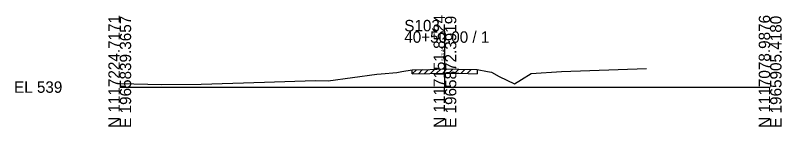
# Model space of a CAD drawing. Extents: x -26 to 163, y -10 to 45020.
# Drawn here: x -25.7 to 162.8, y 490.3 to 517.6 of the extents above; entities that cross this region are included whole.
import ezdxf

# ---------------------------------------------------------------- set-up
doc = ezdxf.new("R2010")
doc.units = 0
for name, color, linetype in [('RD_GPK_XS_Cell', 7, 'Continuous'), ('RD_XS_ExGround', 7, 'Continuous'), ('RD_XS_ExPaveRet', 7, 'Continuous'), ('RD_XS_TX_Elev_EX', 7, 'Continuous')]:
    doc.layers.add(name, color=color, linetype=linetype)

msp = doc.modelspace()

# ---------------------------------------------------------------- linework, layer by layer
at = {"layer": 'RD_GPK_XS_Cell'}
for p, q in [((80, 500), (80, 513.67)), ((0, 500), (80, 500)), ((80, 500), (160, 500))]:
    msp.add_line(p, q, dxfattribs=at)
at = {"layer": 'RD_XS_ExGround'}
for p, q in [((64.33, 503.25), (68.15, 503.55)), ((68.15, 503.55), (69.37, 503.79)), ((69.37, 503.79), (71.96, 504.24)), ((71.96, 504.24), (76.27, 504.35)), ((76.27, 504.35), (79.8, 504.45)), ((79.8, 504.45), (83.42, 504.39)), ((83.42, 504.39), (87.9, 504.28)), ((87.9, 504.28), (90.44, 503.85)), ((90.44, 503.85), (91.45, 503.65)), ((91.45, 503.65), (93.35, 502.63)), ((101.2, 503.35), (108.71, 503.84)), ((108.71, 503.84), (129.6, 504.56)), ((35.64, 501.17), (48.09, 501.62)), ((48.09, 501.62), (51.23, 501.56)), ((51.23, 501.56), (63.26, 503.18)), ((63.26, 503.18), (64.33, 503.25)), ((93.35, 502.63), (97.14, 500.76)), ((97.14, 500.76), (98.82, 501.85)), ((98.82, 501.85), (101.2, 503.35)), ((0, 500.87), (10.34, 500.63)), ((10.34, 500.63), (20.03, 500.69)), ((20.03, 500.69), (35.64, 501.17))]:
    msp.add_line(p, q, dxfattribs=at)
at = {"layer": 'RD_XS_ExPaveRet'}
for p, q in [((71.96, 503.24), (72.98, 504.27)), ((71.96, 503.24), (71.96, 504.24)), ((73.46, 503.28), (74.48, 504.3)), ((74.96, 503.31), (75.98, 504.34)), ((76.27, 503.35), (79.8, 503.45)), ((76.46, 503.35), (77.49, 504.38)), ((77.96, 503.4), (78.99, 504.43)), ((79.46, 503.44), (80.46, 504.44)), ((79.8, 503.45), (83.42, 503.39)), ((80.96, 503.43), (81.94, 504.42)), ((82.46, 503.41), (83.44, 504.39)), ((83.42, 503.39), (87.9, 503.28)), ((83.96, 503.38), (84.93, 504.35)), ((85.46, 503.34), (86.43, 504.32)), ((87.9, 504.28), (87.9, 503.28)), ((71.96, 503.24), (76.27, 503.35))]:
    msp.add_line(p, q, dxfattribs=at)

# ---------------------------------------------------------------- texts
at = {"layer": 'RD_GPK_XS_Cell'}
for s, p in [('N 1117224.7171', (0, 490)), ('E 1965839.3657', (2.8, 490)), ('N 1117151.8524', (80, 490)), ('E 1965872.3919', (82.8, 490)), ('N 1117078.9876', (160, 490)), ('E 1965905.4180', (162.8, 490))]:
    msp.add_text(s, height=2.8, rotation=90, dxfattribs=at).set_placement(p)
for s, p in [('S103', (70, 513.67)), ('40+50.00 / 1', (70, 510.87)), ('EL 539', (-26, 498.6))]:
    msp.add_text(s, height=2.8, dxfattribs=at).set_placement(p)
at = {"layer": 'RD_XS_TX_Elev_EX'}
msp.add_text('543.45', height=0.8, rotation=90, dxfattribs=at).set_placement((79.9, 506.45))

doc.saveas('drawing.dxf')
